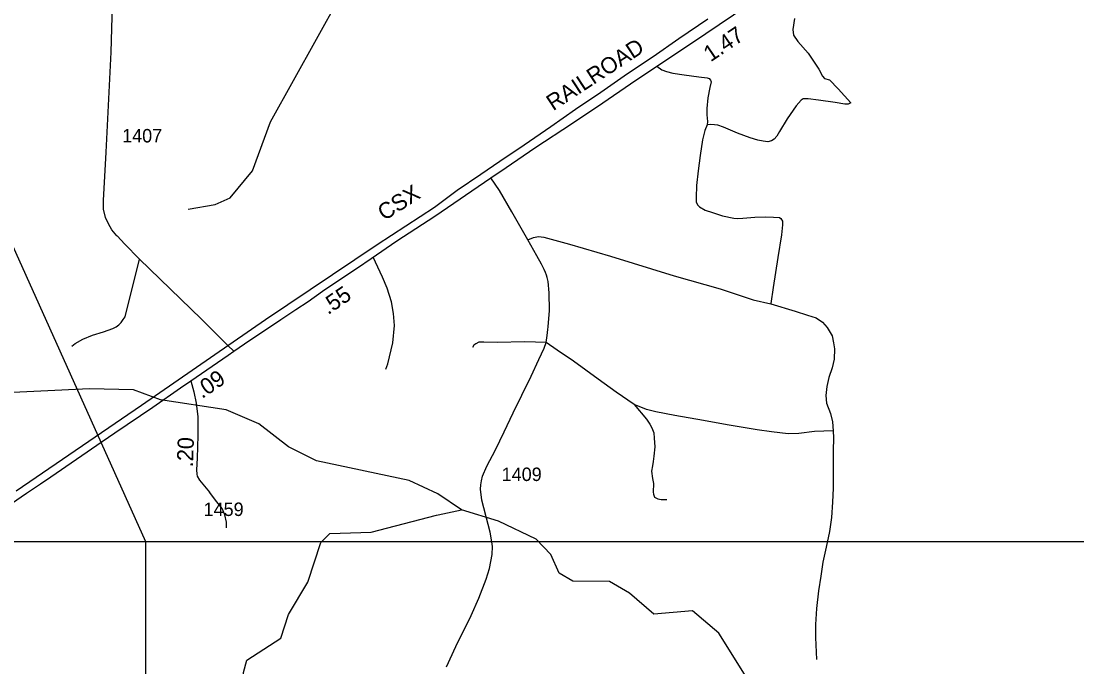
# Model space of a CAD drawing. Extents: x 2290615 to 2522933, y 819489 to 1012715.
# Drawn here: x 2327135 to 2336937, y 982163 to 988157 of the extents above; entities that cross this region are included whole.
import ezdxf

# ---------------------------------------------------------------- set-up
doc = ezdxf.new("R2010")
doc.units = 0
for name, color, linetype in [('Exist Hydrographic Creek Single Shore', 7, 'Continuous'), ('Exist Hydrographic Misc Water Feature', 7, 'Continuous'), ('Exist Railroad Mainline', 7, 'Continuous'), ('Exist Railroad Mainline Label', 7, 'Continuous'), ('Exist Road Non-System Type 51', 7, 'Continuous'), ('Exist Road Primary US Attributed', 7, 'Continuous'), ('Exist Road Primary US Mileage Hundredths English Label', 7, 'Continuous'), ('Exist Road Secondary Mileage Hundredths English Label', 7, 'Continuous'), ('Exist Road Secondary Type 51 Attributed', 7, 'Continuous'), ('Exist Road Secondary Type 51 Number Label', 7, 'Continuous'), ('Map Preparation Inset Cut Line', 7, 'Continuous')]:
    doc.layers.add(name, color=color, linetype=linetype)

msp = doc.modelspace()

# ---------------------------------------------------------------- linework, layer by layer
at = {"layer": 'Exist Hydrographic Creek Single Shore'}
for points in [[(2328686.1, 986411.6), (2328936, 986454.6), (2329077.1, 986516.2), (2329282.2, 986767.6), (2329452.2, 987221), (2330090.1, 988376.5), (2330196.1, 988617.2), (2330264.2, 989178.1), (2330345.2, 989404.6), (2330344.1, 989519.4), (2330284.1, 989704.1), (2330282, 989894.4), (2330804.1, 990940.1), (2330908, 991341.5)], [(2326662.1, 979868.6), (2326737.3, 980150.2), (2326894.3, 980333.8), (2327010.2, 980427.2), (2327816.3, 980611.5), (2327890.3, 980686.7), (2327897.2, 980821.5), (2327995.3, 980920.8), (2328145.2, 980999.2), (2328445.1, 981001.7), (2328868.2, 981157), (2329056.2, 981417.5), (2329154.2, 981667.7), (2329199.3, 982109.5), (2329231.3, 982225.6), (2329546.3, 982429), (2329618.2, 982648.6), (2329798.3, 982948.2), (2329919.3, 983317.5), (2330002.3, 983399.8), (2330385.1, 983412.3), (2330991.3, 983571.8)], [(2333850.3, 982094.2), (2333612.3, 982475), (2333368.2, 982681.7), (2333010.2, 982650.5), (2332782.2, 982848), (2332598.3, 982955.2), (2332256.2, 982957.6), (2332130.1, 983031.2), (2332053.2, 983205.3), (2331918.3, 983347.4), (2331566.2, 983516.7), (2331223.2, 983620.8)]]:
    msp.add_lwpolyline(points, dxfattribs=at)
at = {"layer": 'Exist Hydrographic Misc Water Feature'}
msp.add_line((2331223.2, 983620.8), (2331005.6, 983769.2), dxfattribs=at)
for points in [[(2331005.6, 983769.2), (2330738.2, 983892.9), (2329878.3, 984074.1), (2329618.2, 984204.6), (2329341.2, 984419.7), (2329040.2, 984548.5), (2328430.2, 984641.4), (2328179.2, 984732.9), (2327771.1, 984742.3), (2326863.2, 984701.6), (2326163.1, 984784.4), (2325688.2, 984814.1), (2325420.2, 984927.8), (2325220.1, 984883.4), (2325072, 984755.9), (2325072, 984713.2)], [(2330991.3, 983571.8), (2331007.9, 983575.3), (2331223.2, 983620.8)]]:
    msp.add_lwpolyline(points, dxfattribs=at)
at = {"layer": 'Exist Railroad Mainline'}
msp.add_lwpolyline([(2327090.9, 983797.9), (2328254, 984592.2), (2329403.2, 985388.3), (2330441.3, 986083.2), (2330973.4, 986430.9), (2331184.5, 986587.8), (2331404.7, 986736.6), (2331581.2, 986856.7), (2331805.3, 987009.2), (2332053.2, 987180.3), (2332283.4, 987338.9), (2332517.4, 987497.8), (2332765.2, 987670.7), (2333003.2, 987829.6), (2333241.1, 987994.3), (2333511, 988177.5)], dxfattribs=at)
at = {"layer": 'Exist Road Non-System Type 51'}
for points in [[(2334315, 988182.6), (2334298.6, 988077.9), (2334304.5, 988027.3), (2334347.7, 987969.2), (2334442.9, 987859), (2334542.6, 987711.6), (2334575, 987645.1), (2334594.3, 987625.8), (2334638.9, 987610.9), (2334720.8, 987529), (2334838.1, 987399.7), (2334812.3, 987385.4), (2334782.3, 987385), (2334691.9, 987401.9), (2334537.7, 987424.1), (2334443.6, 987434.9), (2334413.8, 987436.6), (2334395.6, 987434.3), (2334375.9, 987422.1), (2334330.5, 987369.6), (2334248, 987248.7), (2334177.3, 987133.7), (2334150, 987087.6), (2334126.2, 987061.2), (2334100.5, 987044.9), (2334068.6, 987036.6), (2334024.5, 987044), (2333974.4, 987051.3), (2333904.3, 987072.4), (2333787.6, 987117.1), (2333657, 987171.5), (2333602.8, 987190.9), (2333572.8, 987194.5), (2333536.7, 987198), (2333504.8, 987195.7)], [(2333036.3, 987739.9), (2333084.8, 987704.5), (2333126.8, 987689), (2333187.1, 987673.9), (2333291.3, 987657), (2333427.4, 987640.8), (2333503.5, 987629.7), (2333523.5, 987623.9), (2333535.7, 987610), (2333542.1, 987592), (2333530.5, 987541.9), (2333511.8, 987443.7), (2333501, 987345.6), (2333501.6, 987287.6), (2333506.3, 987225.8), (2333504.8, 987195.7)], [(2333036.3, 987739.9), (2333084.8, 987704.5), (2333126.8, 987689), (2333187.1, 987673.9), (2333291.3, 987657), (2333427.4, 987640.8), (2333503.5, 987629.7), (2333523.5, 987623.9), (2333535.7, 987610), (2333542.1, 987592), (2333530.5, 987541.9), (2333511.8, 987443.7), (2333501, 987345.6), (2333501.6, 987287.6), (2333506.3, 987225.8), (2333504.8, 987195.7)], [(2333504.8, 987195.7), (2333481.4, 987141.5), (2333460.5, 987055.2), (2333440.3, 986909.1), (2333419.9, 986768.7), (2333405.5, 986632.7), (2333401, 986518.6), (2333403.3, 986480.7), (2333415.8, 986450.8), (2333431.9, 986433), (2333486.3, 986403.7), (2333552.5, 986380.4), (2333646.9, 986349.6), (2333753.2, 986328.8), (2333787.1, 986325.2), (2333835.1, 986327.8), (2333946.9, 986337.2), (2334046.9, 986340.3), (2334119, 986337.3), (2334175, 986334), (2334189.1, 986326.1), (2334203.4, 986300.3), (2334203.8, 986266.3), (2334195, 986174.3), (2334159.5, 985961.9), (2334116.9, 985685.4), (2334096.6, 985535.1)], [(2333504.8, 987195.7), (2333481.4, 987141.5), (2333460.5, 987055.2), (2333440.3, 986909.1), (2333419.9, 986768.7), (2333405.5, 986632.7), (2333401, 986518.6), (2333403.3, 986480.7), (2333415.8, 986450.8), (2333431.9, 986433), (2333486.3, 986403.7), (2333552.5, 986380.4), (2333646.9, 986349.6), (2333753.2, 986328.8), (2333787.1, 986325.2), (2333835.1, 986327.8), (2333946.9, 986337.2), (2334046.9, 986340.3), (2334119, 986337.3), (2334175, 986334), (2334189.1, 986326.1), (2334203.4, 986300.3), (2334203.8, 986266.3), (2334195, 986174.3), (2334159.5, 985961.9), (2334116.9, 985685.4), (2334096.6, 985535.1)], [(2331840.8, 986126.9), (2331892.5, 986149.6), (2331939, 986157.3), (2331988.5, 986152.7), (2332227.2, 986086), (2332606.8, 985974.4), (2333197.7, 985793.4), (2333623.8, 985670.9), (2333930.9, 985569.3), (2334096.2, 985531.7), (2334322.9, 985465.4), (2334436.1, 985428.1), (2334515.1, 985403.3), (2334574, 985363), (2334618.9, 985311.8), (2334663.9, 985235.9), (2334677.8, 985169.2), (2334685.5, 985116.5), (2334682.4, 985020), (2334663.8, 984937.8), (2334634.3, 984849.4), (2334614.2, 984764.1), (2334604.9, 984681.9), (2334611.1, 984609.1), (2334649.8, 984514.5), (2334666.7, 984436.1), (2334674.7, 984354.4)], [(2327606.3, 985139), (2327636, 985165.2), (2327709.6, 985206), (2327797.2, 985241.1), (2327898.8, 985272.1), (2327986.3, 985303.1), (2328018.3, 985319.4), (2328041.9, 985337.6), (2328063.8, 985359.9), (2328083.6, 985386.1), (2328101.3, 985412.3), (2328109, 985440.2), (2328156.8, 985634.7), (2328233.3, 985947.6)], [(2327606.3, 985139), (2327636, 985165.2), (2327709.6, 985206), (2327797.2, 985241.1), (2327898.8, 985272.1), (2327986.3, 985303.1), (2328018.3, 985319.4), (2328041.9, 985337.6), (2328063.8, 985359.9), (2328083.6, 985386.1), (2328101.3, 985412.3), (2328109, 985440.2), (2328156.8, 985634.7), (2328233.3, 985947.6)], [(2330521.8, 984926.4), (2330541.3, 984976.6), (2330587.1, 985171.2), (2330603.3, 985331.1), (2330592.1, 985443.1), (2330573, 985552.8), (2330533.6, 985678.4), (2330490.6, 985779.9), (2330404.3, 985966.2)], [(2330521.8, 984926.4), (2330541.3, 984976.6), (2330587.1, 985171.2), (2330603.3, 985331.1), (2330592.1, 985443.1), (2330573, 985552.8), (2330533.6, 985678.4), (2330490.6, 985779.9), (2330404.3, 985966.2)], [(2332826.1, 984598.1), (2332658.8, 984714), (2332491.4, 984834), (2332263.4, 985001.1), (2332112.3, 985103.4), (2332009.3, 985174.2), (2331811.4, 985179.8), (2331555.4, 985174.7), (2331431.5, 985177.2), (2331383.5, 985176.6), (2331355.7, 985160.3), (2331337.7, 985150.1), (2331326.1, 985125.8)], [(2334674.7, 984354.4), (2334500.8, 984346.2), (2334357, 984328.5), (2334257.1, 984325.4), (2334102.9, 984343.5), (2333968.8, 984362), (2333690.2, 984408.5), (2333469.7, 984449.9), (2333205.3, 984496.6), (2333027, 984530.5), (2332940.6, 984553.3), (2332826.1, 984598.1)], [(2332826.1, 984598.1), (2332941.8, 984461.5), (2332972.3, 984415.8), (2332990.7, 984380.1), (2333009.2, 984334.2), (2333013.9, 984284.4), (2333018.9, 984206.4), (2333007.9, 984118.3), (2333004.6, 984068.3), (2332997, 984028.2), (2332987.6, 983980.2), (2332998.4, 983912.4), (2333007, 983864.3), (2333003.9, 983784.3), (2333006.1, 983764.4), (2333014.4, 983738.5), (2333046.6, 983722.8), (2333078.7, 983717.4), (2333128.7, 983717.8)], [(2334674.7, 984354.4), (2334500.8, 984346.2), (2334357, 984328.5), (2334257.1, 984325.4), (2334102.9, 984343.5), (2333968.8, 984362), (2333690.2, 984408.5), (2333469.7, 984449.9), (2333205.3, 984496.6), (2333027, 984530.5), (2332940.6, 984553.3), (2332826.1, 984598.1)], [(2332826.1, 984598.1), (2332941.8, 984461.5), (2332972.3, 984415.8), (2332990.7, 984380.1), (2333009.2, 984334.2), (2333013.9, 984284.4), (2333018.9, 984206.4), (2333007.9, 984118.3), (2333004.6, 984068.3), (2332997, 984028.2), (2332987.6, 983980.2), (2332998.4, 983912.4), (2333007, 983864.3), (2333003.9, 983784.3), (2333006.1, 983764.4), (2333014.4, 983738.5), (2333046.6, 983722.8), (2333078.7, 983717.4), (2333128.7, 983717.8)], [(2334674.7, 984354.4), (2334677.5, 984288.5), (2334675, 984168.3), (2334672.9, 984016.3), (2334673, 983822.4), (2334668.7, 983690.4), (2334658.3, 983548.3), (2334640, 983420), (2334609.8, 983273.7), (2334579.3, 983133.4), (2334558.9, 983003.3), (2334538.6, 982868.9), (2334520.5, 982704.9), (2334510.4, 982556.8), (2334509.8, 982436.7), (2334518.2, 982230.9)], [(2334674.7, 984354.4), (2334677.5, 984288.5), (2334675, 984168.3), (2334672.9, 984016.3), (2334673, 983822.4), (2334668.7, 983690.4), (2334658.3, 983548.3), (2334640, 983420), (2334609.8, 983273.7), (2334579.3, 983133.4), (2334558.9, 983003.3), (2334538.6, 982868.9), (2334520.5, 982704.9), (2334510.4, 982556.8), (2334509.8, 982436.7), (2334518.2, 982230.9)], [(2329042.1, 983452.9), (2329041.5, 983506.9), (2329026.7, 983574.7), (2329002.1, 983632.5), (2328953.5, 983693.9), (2328883.7, 983785.1)], [(2329042.1, 983452.9), (2329041.5, 983506.9), (2329026.7, 983574.7), (2329002.1, 983632.5), (2328953.5, 983693.9), (2328883.7, 983785.1)]]:
    msp.add_lwpolyline(points, dxfattribs=at)
at = {"layer": 'Exist Road Primary US Attributed'}
for points in [[(2331497.2, 986701.6), (2331639.8, 986799.3), (2331905.7, 986980.5), (2332254.8, 987210.7), (2332536.4, 987399.9), (2332792.3, 987575), (2333036.3, 987739.9), (2333357.8, 987951.9), (2333748.5, 988216.5), (2333934.8, 988342.6), (2334059.9, 988424.2), (2334337.6, 988615.4), (2334781.9, 988910.8), (2335150.8, 989161.1), (2335563.3, 989436.1), (2335924.3, 989680.3), (2336243.8, 989890.1), (2336452.1, 990032.6), (2336604.7, 990130.3), (2336787.3, 990254.5), (2336934.1, 990354.4), (2337075, 990446.1)], [(2329109.9, 985091.8), (2329209, 985161.6), (2329547.9, 985385.9), (2329686.2, 985481.1), (2329798.8, 985553.8), (2329934.2, 985649.1), (2330086, 985753.3), (2330256.8, 985866), (2330386.2, 985953.8), (2330623.7, 986116.8), (2330975.4, 986347.5), (2331497.2, 986701.6)], [(2328711.4, 984819), (2329058.8, 985055.9), (2329109.9, 985091.8)], [(2325145.8, 982370.8), (2325219.6, 982434.3), (2325349, 982521.9), (2325438.2, 982585.9), (2325584, 982688.6), (2325750.7, 982797.3), (2325883.1, 982883.7), (2325983.5, 982957.4), (2326171, 983082.4), (2326281.1, 983156.9), (2326677.8, 983436.2), (2326863.8, 983556.8), (2327184.8, 983776.6), (2327314.3, 983861.5), (2327412.5, 983927), (2327886.5, 984253.6), (2328004, 984335.5), (2328358.9, 984574.5), (2328614.8, 984753.2), (2328711.4, 984819)]]:
    msp.add_lwpolyline(points, dxfattribs=at)
at = {"layer": 'Exist Road Secondary Type 51 Attributed'}
for points in [[(2329054, 985146.4), (2328807.4, 985394.3), (2328233.3, 985947.6), (2328095.7, 986089.5), (2328029.8, 986160.1), (2328025.1, 986163.1), (2327978.5, 986220.6), (2327945.9, 986274.3), (2327917.8, 986335.1), (2327900.9, 986411.8), (2327899.4, 986493.2), (2327923.9, 986941.3), (2327970.9, 987868.1), (2327984.1, 988308.1)], [(2331083.8, 982161.6), (2331171.6, 982352.7), (2331313.6, 982639.8), (2331384.7, 982800.2), (2331451.9, 982975.8), (2331483, 983074.5), (2331507.5, 983205.2), (2331511.4, 983278.9), (2331506.2, 983322.9), (2331490.7, 983412.2), (2331413.1, 983709.8), (2331399.9, 983811.1), (2331402.1, 983852.7), (2331408.6, 983890.3), (2331420.2, 983931.7), (2331457.7, 984026.1), (2331540.5, 984177.5), (2331619.5, 984343.7), (2331703.2, 984520.6), (2331783.4, 984683.6), (2331871.3, 984862.5), (2331941.4, 985015.3), (2331992.1, 985119.8), (2332009.3, 985174.2), (2332018.7, 985238.2), (2332024, 985294.2), (2332027.6, 985318.2), (2332041.7, 985470.5), (2332038.3, 985634.3), (2332027.9, 985740.4), (2332018.9, 985776.6), (2332012.4, 985798.6), (2332003.4, 985824.5), (2331990.4, 985851.7), (2331967.2, 985902.1), (2331923.5, 985979.6), (2331840.8, 986126.9), (2331690.5, 986388.2), (2331576, 986585.9), (2331497.2, 986701.6)], [(2329109.9, 985091.8), (2329054, 985146.4)], [(2328711.4, 984819), (2328738.5, 984715.4), (2328761.6, 984611.5), (2328777.1, 984483.9), (2328777, 984311.8), (2328769.1, 984099.7), (2328764.4, 983991.7), (2328766.8, 983951.8), (2328771, 983931.9), (2328791.3, 983896.2), (2328883.7, 983785.1)]]:
    msp.add_lwpolyline(points, dxfattribs=at)
at = {"layer": 'Map Preparation Inset Cut Line'}
for points in [[(2356768.7, 983323.8), (2328294.4, 983323.8), (2321803.3, 997760.3), (2321797.8, 1007474.2), (2338139.7, 1007474.2), (2356768.7, 1000715)], [(2328294.4, 983323.8), (2317413.3, 983323.8), (2317413.3, 972600.6), (2328294.4, 972600.6)]]:
    msp.add_lwpolyline(points, close=True, dxfattribs=at)

# ---------------------------------------------------------------- texts
at = {"layer": 'Exist Railroad Mainline Label'}
for s, rotation, p in [('RAILROAD', 33.12952, (2332074.7, 987320.2)), ('CSX', 32.5381, (2330506.9, 986299.5))]:
    msp.add_text(s, height=150, rotation=rotation, dxfattribs=at).set_placement(p)
at = {"layer": 'Exist Road Primary US Mileage Hundredths English Label'}
for s, rotation, p in [('1.47', 34.109, (2333536.4, 987773.6)), ('.55', 34.47903, (2329984.9, 985427)), ('.09', 34.28736, (2328815.6, 984648))]:
    msp.add_text(s, height=150, rotation=rotation, dxfattribs=at).set_placement(p)
at = {"layer": 'Exist Road Secondary Mileage Hundredths English Label'}
msp.add_text('.20', height=150, rotation=87.86684, dxfattribs=at).set_placement((2328730.1, 984013.6))
at = {"layer": 'Exist Road Secondary Type 51 Number Label'}
msp.add_text('1407', height=125, dxfattribs=at).set_placement((2328073.3, 987030.8))
for s, p in [('1409', (2331596.6, 983887.8)), ('1459', (2328829.4, 983563.1))]:
    msp.add_text(s, height=125, rotation=360, dxfattribs=at).set_placement(p)

doc.saveas('drawing.dxf')
